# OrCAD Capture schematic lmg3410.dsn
size Custom; title: LMG3410; rev: 1.0; note: SNOSD10A
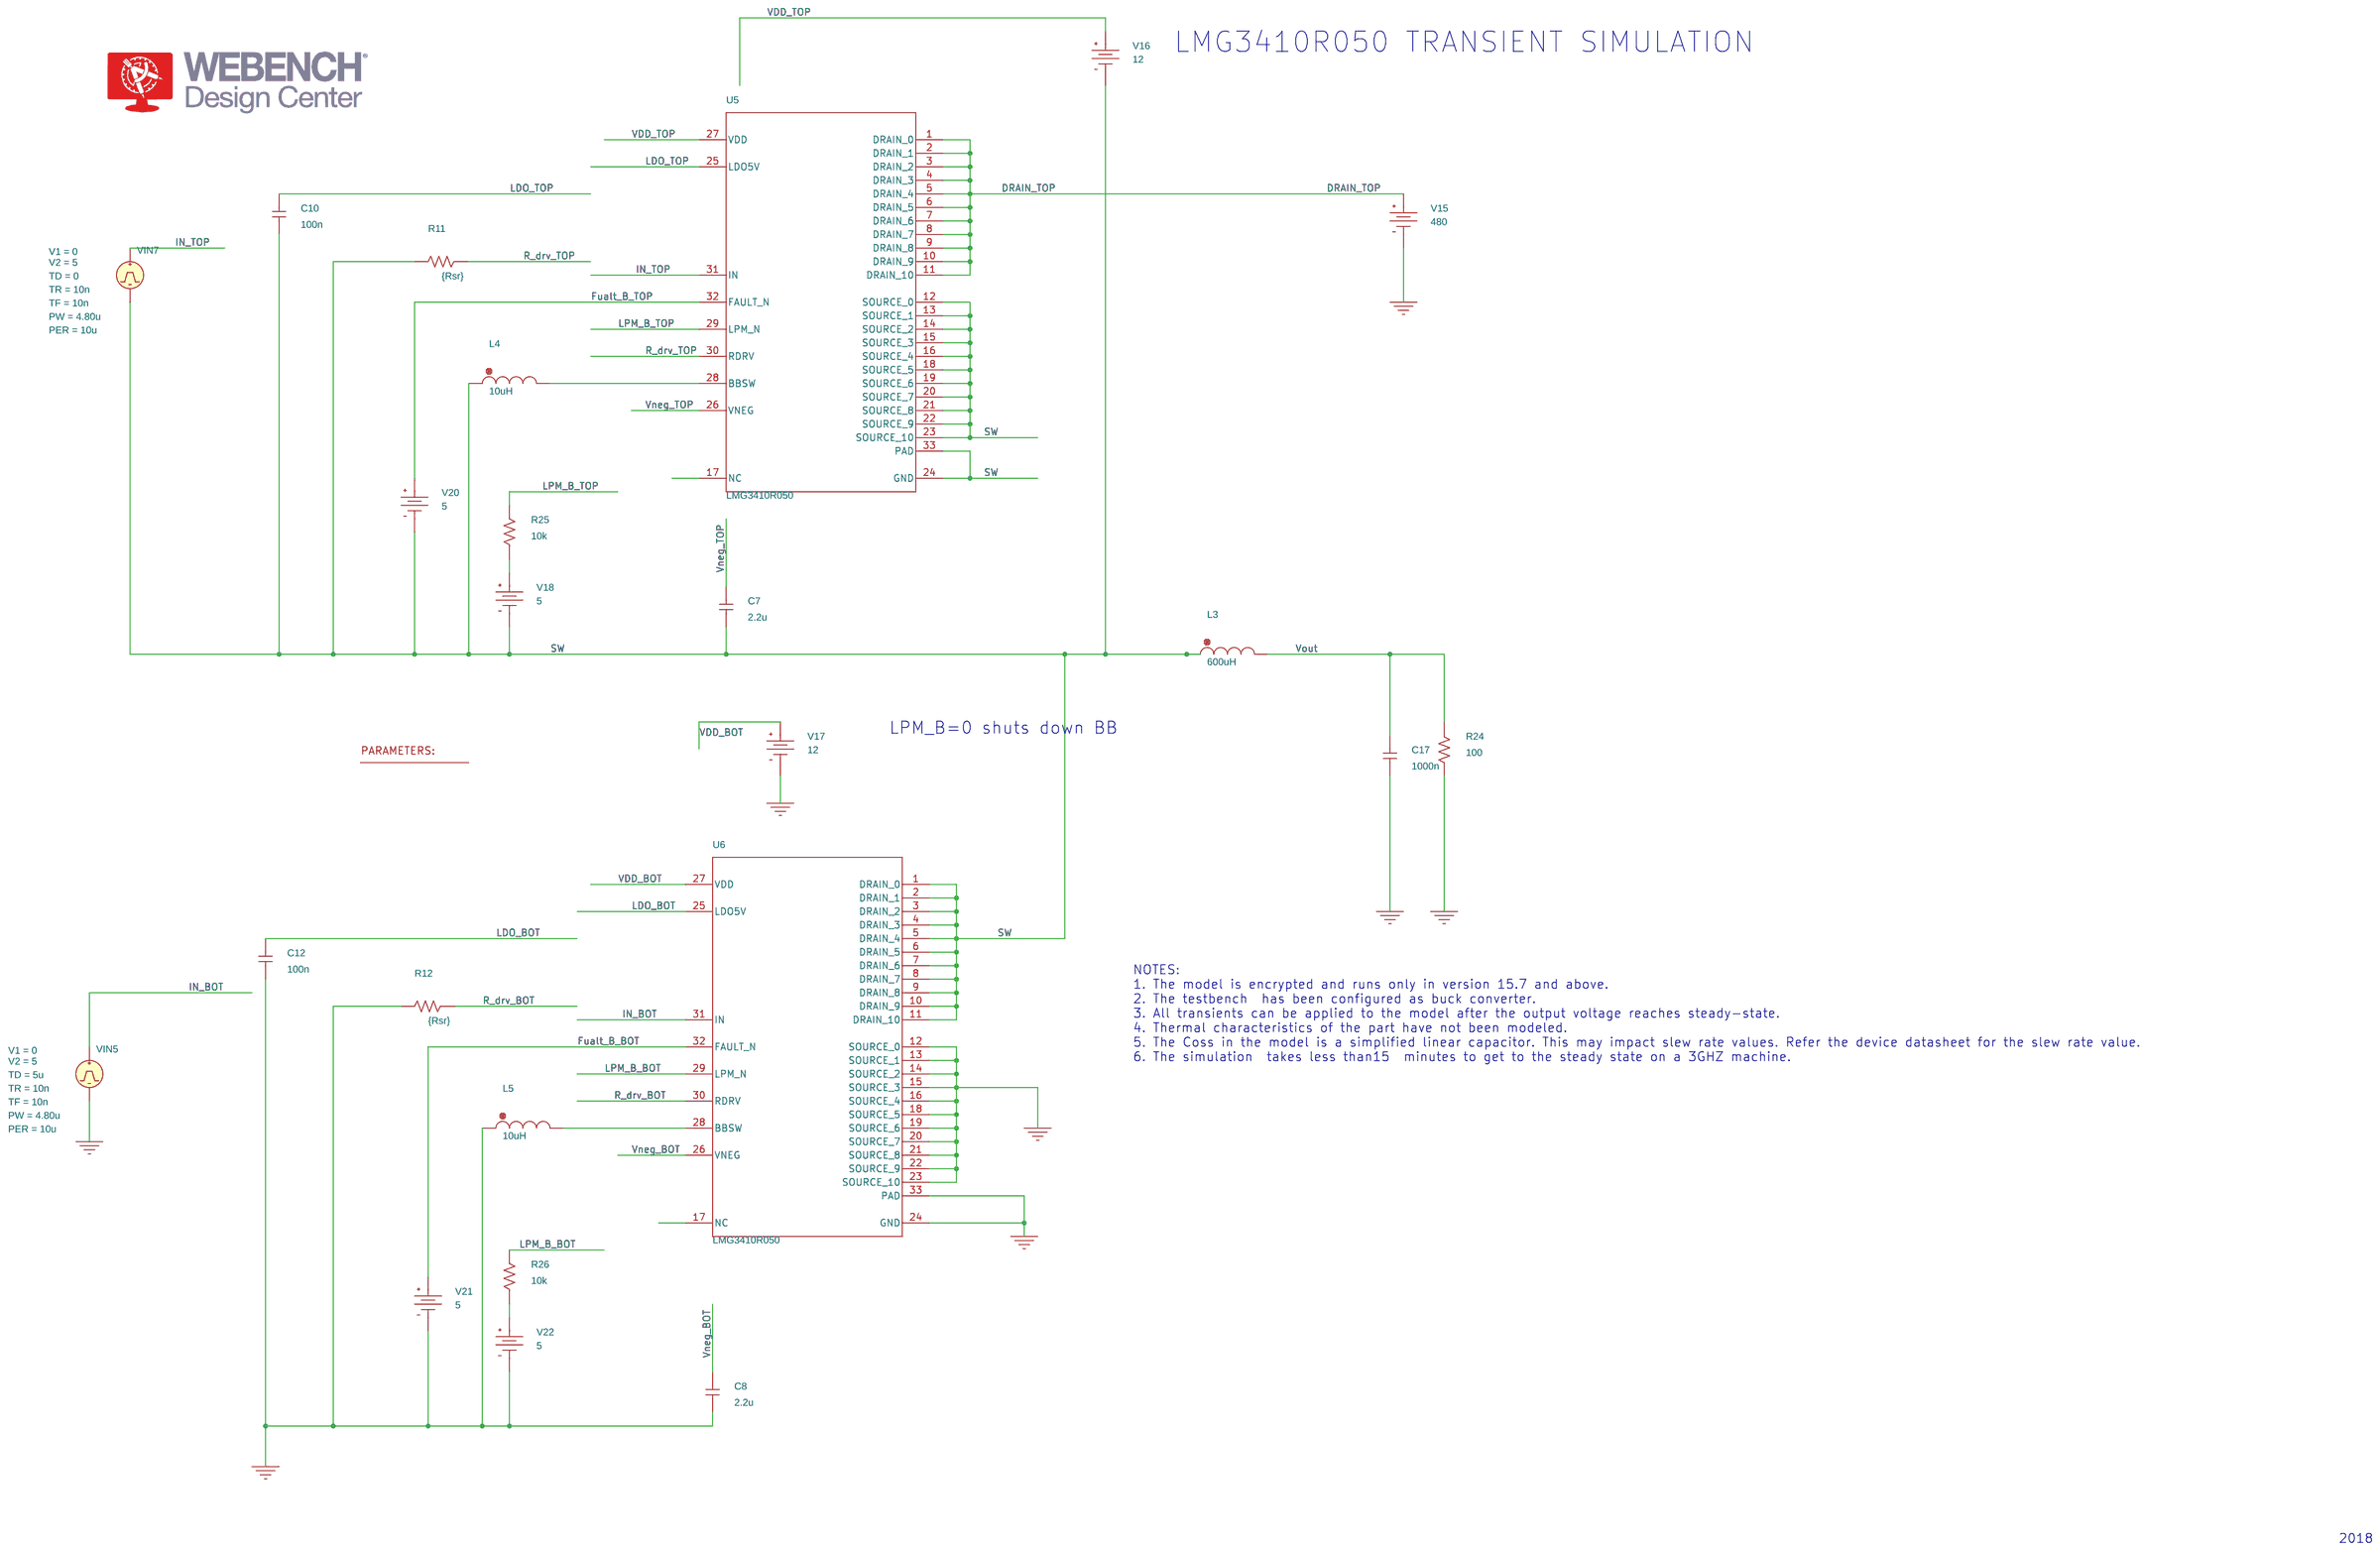
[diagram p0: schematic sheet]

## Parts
1  PARAM
C7  2.2u  [RAD/CK05]
C8  2.2u  [RAD/CK05]
C10  100n  [RAD/CK05]
C12  100n  [RAD/CK05]
C17  1000n  [RAD/CK05]
L3  600uH  [DISC/.350x.175/LS.200x.100/.034]
L4  10uH  [DISC350x175LS200x100034]
L5  10uH  [DISC350x175LS200x100034]
R11  {Rsr}  [AX/RC05]
R12  {Rsr}  [AX/RC05]
R24  100  [AX/RC05]
R25  10k  [AXRC05]
R26  10k  [AXRC05]
U5  LMG3410R050  [RWH0032A]
U6  LMG3410R050  [RWH0032A]
V15  VDC
V16  VDC
V17  VDC
V18  VDC
V20  VDC
V21  VDC
V22  VDC
VIN5  VPULSE
VIN7  VPULSE

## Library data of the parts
1 = PARAM: Rsr: 150k
C7 C8 C10 C12 C17 = C
L3-L5 = L
R11 R12 R24-R26 = R
U5 U6 = LMG3410R050
V15 = VDC: DC: 480
V16 V17 = VDC: DC: 12
V18 V20-V22 = VDC: DC: 5
VIN5 = VPULSE: PER: 10u; PW: 4.80u; TD: 5u; TF: 10n; TR: 10n; V1: 0; V2: 5
VIN7 = VPULSE: PER: 10u; PW: 4.80u; TD: 0; TF: 10n; TR: 10n; V1: 0; V2: 5

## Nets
VDD_BOT: U6.27(VDD) V17.0(+)
VDD_TOP: U5.27(VDD) V16.0(+)
0: C8.1 C12.1 C17.1 L5.1 R12.2 R24.2 U6.12(SOURCE_0) U6.13(SOURCE_1) U6.14(SOURCE_2) U6.15(SOURCE_3) U6.16(SOURCE_4) U6.18(SOURCE_5) U6.19(SOURCE_6) U6.20(SOURCE_7) U6.21(SOURCE_8) U6.22(SOURCE_9) U6.23(SOURCE_10) U6.24(GND) U6.33(PAD) V15.1(-) V17.1(-) V21.1(-) V22.1(-) VIN5.2(-)
DRAIN_TOP: U5.1(DRAIN_0) U5.2(DRAIN_1) U5.3(DRAIN_2) U5.4(DRAIN_3) U5.5(DRAIN_4) U5.6(DRAIN_5) U5.7(DRAIN_6) U5.8(DRAIN_7) U5.9(DRAIN_8) U5.10(DRAIN_9) U5.11(DRAIN_10) V15.0(+)
Fualt_B_BOT: U6.32(FAULT_N) V21.0(+)
Fualt_B_TOP: U5.32(FAULT_N) V20.0(+)
IN_BOT: U6.31(IN) VIN5.1(+)
IN_TOP: U5.31(IN) VIN7.1(+)
LDO_BOT: C12.2 U6.25(LDO5V)
LDO_TOP: C10.2 U5.25(LDO5V)
LPM_B_BOT: R26.2 U6.29(LPM_N)
LPM_B_TOP: R25.2 U5.29(LPM_N)
R_drv_BOT: R12.1 U6.30(RDRV)
R_drv_TOP: R11.1 U5.30(RDRV)
SW: C7.1 C10.1 L3.1 L4.1 R11.2 U5.12(SOURCE_0) U5.13(SOURCE_1) U5.14(SOURCE_2) U5.15(SOURCE_3) U5.16(SOURCE_4) U5.18(SOURCE_5) U5.19(SOURCE_6) U5.20(SOURCE_7) U5.21(SOURCE_8) U5.22(SOURCE_9) U5.23(SOURCE_10) U5.24(GND) U5.33(PAD) U6.1(DRAIN_0) U6.2(DRAIN_1) U6.3(DRAIN_2) U6.4(DRAIN_3) U6.5(DRAIN_4) U6.6(DRAIN_5) U6.7(DRAIN_6) U6.8(DRAIN_7) U6.9(DRAIN_8) U6.10(DRAIN_9) U6.11(DRAIN_10) V16.1(-) V18.1(-) V20.1(-) VIN7.2(-)
Vneg_BOT: C8.2 U6.26(VNEG)
Vneg_TOP: C7.2 U5.26(VNEG)
Vout: C17.2 L3.2 R24.1
N368251: L5.2 U6.28(BBSW)
N14589354: L4.2 U5.28(BBSW)
N14589886: R25.1 V18.0(+)
N14590195: R26.1 V22.0(+)

Not connected (* = marked no-connect by the designer): U5 17(NC); U6 17(NC)

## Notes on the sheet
- LMG3410R050 TRANSIENT SIMULATION
- LPM_B=0 shuts down BB
- NOTES:
  1. The model is encrypted and runs only in version 15.7 and above.
  2. The testbench  has been configured as buck converter.
  3. All transients can be applied to the model after the output voltage reaches steady-state.
  4. Thermal characteristics of the part have not been modeled.
  5. The Coss in the model is a simplified linear capacitor. This may impact slew rate values. Refer the device datasheet for the slew rate value.
  6. The simulation  takes less than15  minutes to get to the steady state on a 3GHZ machine.
- 2018
